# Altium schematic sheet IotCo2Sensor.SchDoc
size A4
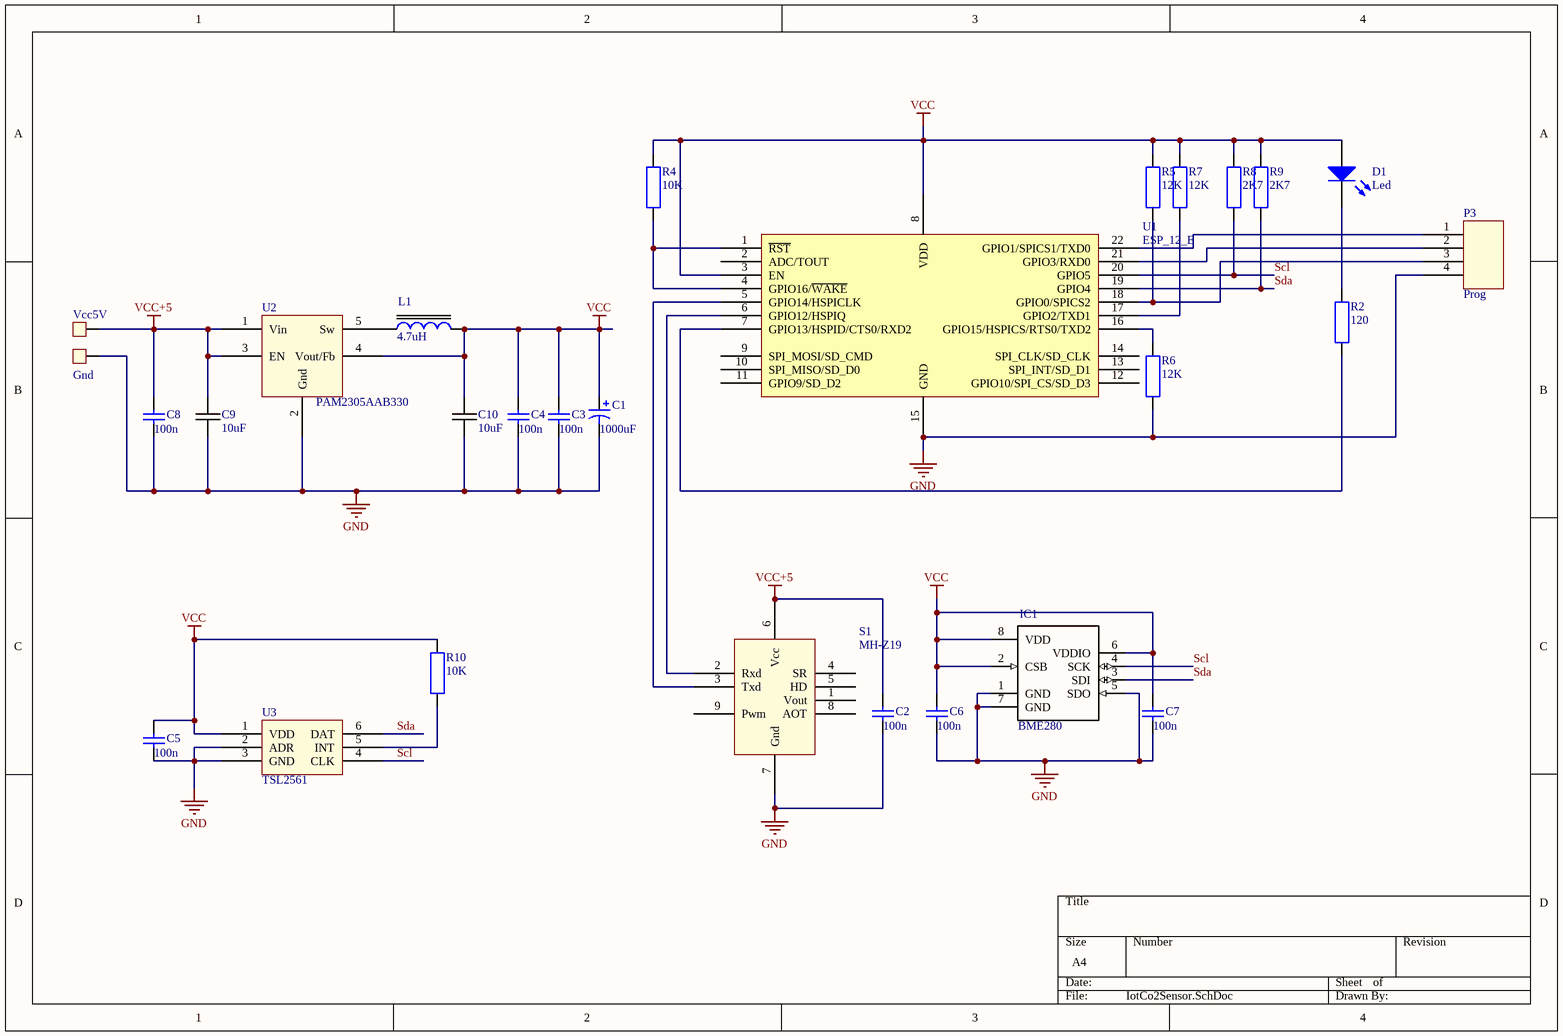
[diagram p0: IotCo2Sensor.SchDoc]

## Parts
C1  value 1000uF  [X]  (hidden comment: T491X)
C2  value 100n  [1608[0603]]  (hidden comment: Cap Semi)
C3  value 100n  [1608[0603]]  (hidden comment: Cap Semi)
C4  value 100n  [1608[0603]]  (hidden comment: Cap Semi)
C5  value 100n  [1608[0603]]  (hidden comment: Cap Semi)
C6  value 100n  [1608[0603]]  (hidden comment: Cap Semi)
C7  value 100n  [1608[0603]]  (hidden comment: Cap Semi)
C8  value 100n  [1608[0603]]  (hidden comment: Cap Semi)
C9  10uF  [0603C-GENERIC]
C10  10uF  [0603C-GENERIC]
D1  Led  [LED1608]
IC1  BME280  [BME280]
L1  4.7uH  [INDC2016X100N]
P3  Prog  [Header4x1.27mm SMD]
R2  value 120  [RES0603R]  (hidden comment: Resistor)
R4  value 10K  [RES0603R]  (hidden comment: Resistor)
R5  value 12K  [RES0603R]  (hidden comment: Resistor)
R6  value 12K  [RES0603R]  (hidden comment: Resistor)
R7  value 12K  [RES0603R]  (hidden comment: Resistor)
R8  value 2K7  [RES0603R]  (hidden comment: Resistor)
R9  value 2K7  [RES0603R]  (hidden comment: Resistor)
R10  value 10K  [RES0603R]  (hidden comment: Resistor)
S1  MH-Z19  [MH-Z19]
TP1  Vcc5V  [TpSmd2.0]
TP2  Gnd  [TpSmd2.0]
U1  ESP_12_E  [ESP_12_E]
U2  PAM2305AAB330  [SOT95P280X145-5N]
U3  TSL2561  [DFN6-2x2]

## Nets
GND: C1.2 C2.1 C3.1 C4.1 C5.1 C6.1 C7.1 C8.1 C9.2 C10.2 IC1.1(GND) IC1.5(SDO) IC1.7(GND) P3.4 R6.2 S1.7(Gnd) TP2.1 U1.15(GND) U2.2(Gnd) U3.2(ADR) U3.3(GND)
VCC: C1.1 C3.2 C4.2 C5.2 C6.2 C7.2 C10.1 D1.1(A) IC1.2(CSB) IC1.6(VDDIO) IC1.8(VDD) L1.2 R4.1 R5.1 R7.1 R8.1 R9.1 R10.1 U1.3(EN) U1.8(VDD) U2.4(Vout/Fb) U3.1(VDD)
VCC+5: C2.2 C8.2 C9.1 S1.6(Vcc) TP1.1 U2.1(Vin) U2.3(EN)
Scl: IC1.4(SCK) R8.2 U1.20(GPIO5) U3.4(CLK)
Sda: IC1.3(SDI) R9.2 U1.19(GPIO4) U3.6(DAT)
NetD1_2: D1.2(K) R2.1
NetL1_1: L1.1 U2.5(Sw)
NetP3_1: P3.1 U1.22(GPIO1/SPICS1/TXD0)
NetP3_2: P3.2 U1.21(GPIO3/RXD0)
NetP3_3: P3.3 R5.2 U1.18(GPIO0/SPICS2)
NetR2_2: R2.2 U1.7(GPIO13/HSPID/CTS0/RXD2)
NetR4_2: R4.2 U1.1(~{RST}) U1.4(GPIO16/~{WAKE})
NetR6_1: R6.1 U1.16(GPIO15/HSPICS/RTS0/TXD2)
NetR7_2: R7.2 U1.17(GPIO2/TXD1)
NetR10_2: R10.2 U3.5(INT)
NetS1_2: S1.2(Rxd) U1.6(GPIO12/HSPIQ)
NetS1_3: S1.3(Txd) U1.5(GPIO14/HSPICLK)

Not connected (* = marked no-connect by the designer): S1 1(Vout) 4(SR) 5(HD) 8(AOT) 9(Pwm); U1 2(ADC/TOUT) 9(SPI_MOSI/SD_CMD) 10(SPI_MISO/SD_D0) 11(GPIO9/SD_D2) 12(GPIO10/SPI_CS/SD_D3) 13(SPI_INT/SD_D1) 14(SPI_CLK/SD_CLK)

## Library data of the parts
C1 = T491X: Solid Tantalum Chip Capacitor, Standard T491 Series - Industrial Grade; PCB_Layout: Round Glue Pad at 2.9 ±0.1mm in diameter at KEMET's option
C2-C8 = Cap Semi: Capacitor (Semiconductor SIM Model)
C9 C10 = 0603C-10UF-6V3-X5R-MUR: CAPACITOR 0603 CERAMIC; Manufacturer: Murata Electronics North America; Manufacturer Part Number: GRM188R60J106ME47D; Reel: C24
D1 = Led: pin to pad: 1>A 2>K
IC1 = BME280: Integrated pressure, humidity and temperature sensor; 8-pin 2.5x2.5x0.93mm LGA; MF: Bosch
L1 = LQM2MPN4R7MG0L: Inductor Power Chip Shielded Multi-Layer 4.7uH 20% 1MHz Ferrite 1.1A 175mOhm DCR 0806 Embossed T/R; MF: Murata
P3 = Header4x1.27mm
TP1 TP2 = TestPad
U1 = ESP_12_E: ESP-12 Wi-Fi Module by AI-Thinker; IC: ESP8266-EX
